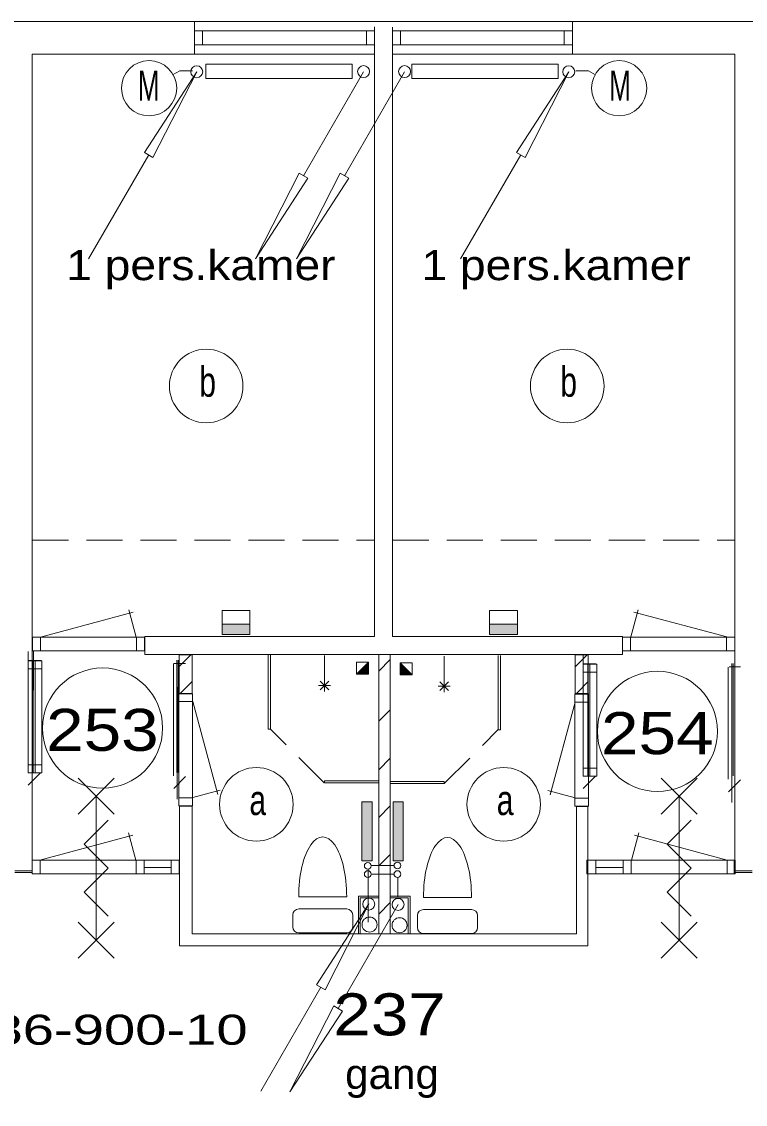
# Model space of a CAD drawing. Extents: x 295824 to 414724, y 24924 to 109024.
# Drawn here: x 314001 to 320029, y 95404 to 104418 of the extents above; entities that cross this region are included whole.
import ezdxf
from ezdxf.enums import TextEntityAlignment as Align

# ---------------------------------------------------------------- set-up
doc = ezdxf.new("R2010")
doc.units = 0
doc.header["$LTSCALE"] = 100
doc.linetypes.add('LONG_DASHED', pattern=[7.5, 6, -1.5])
doc.linetypes.add('MEDIUM_DASHED', pattern=[4.5, 3, -1.5])
doc.layers.add('16', color=7, linetype='Continuous', lineweight=13)
doc.layers.add('61', color=7, linetype='Continuous', lineweight=13)

msp = doc.modelspace()

# ---------------------------------------------------------------- hatches: boundary and pattern name
at = {"layer": '16'}
for points in [[(315902.2, 99315.2), (315670.7, 99315.2), (315670.7, 99401.7), (315902.2, 99401.7)], [(318129.9, 99315.2), (317898.4, 99315.2), (317898.4, 99401.7), (318129.9, 99401.7)], [(316835.4, 97923), (316920.8, 97923), (316920.8, 97430.8), (316835.4, 97430.8)], [(317094.6, 97923), (317180, 97923), (317180, 97430.8), (317094.6, 97430.8)]]:
    msp.add_hatch(color=256, dxfattribs=at).paths.add_polyline_path(points)
at = {"layer": '61'}
for points in [[(316790.6, 98985.1), (316890.6, 99085.1), (316890.6, 98985.1)], [(317253, 98979.7), (317153, 99079.7), (317153, 98979.7)]]:
    msp.add_hatch(color=256, dxfattribs=at).paths.add_polyline_path(points)

# ---------------------------------------------------------------- linework, layer by layer
at = {"layer": '16'}
for p, q in [((316849.4, 104000.9), (316349.4, 103134.9)), ((317191, 104000.9), (316691, 103134.9)), ((314559.2, 102441.9), (315059.2, 103307.9)), ((317657.6, 102441.9), (318157.6, 103307.9)), ((315670.7, 99401.7), (315670.7, 99515.6)), ((317898.4, 99401.7), (317898.4, 99515.6)), ((316887.6, 96920.1), (316887.6, 97360.2)), ((317103, 97392), (316911.2, 97392)), ((317136.2, 97067.7), (316636.2, 96201.7)), ((315992.3, 95512.9), (316492.3, 96378.9))]:
    msp.add_line(p, q, dxfattribs=at)
at = {"layer": '16', "linetype": 'LONG_DASHED'}
for p, q in [((316911.4, 97321.2), (317102.9, 97321.2)), ((317133.8, 97131.9), (317133.8, 97295.5))]:
    msp.add_line(p, q, dxfattribs=at)
at = {"layer": '16'}
for points in [[(315536, 103945.4), (316755.3, 103945.4), (316755.3, 104063.3), (315536, 104063.3)], [(317251.6, 103945.4), (318470.9, 103945.4), (318470.9, 104063.3), (317251.6, 104063.3)], [(315459.2, 104000.9), (315095.2, 103286.9), (315023.2, 103328.9)], [(318557.6, 104000.9), (318193.6, 103286.9), (318121.6, 103328.9)], [(315949.4, 102441.9), (316313.4, 103155.9), (316385.4, 103113.9)], [(316291, 102441.9), (316655, 103155.9), (316727, 103113.9)], [(315902.2, 99315.2), (315670.7, 99315.2), (315670.7, 99401.7), (315902.2, 99401.7)], [(318129.9, 99315.2), (317898.4, 99315.2), (317898.4, 99401.7), (318129.9, 99401.7)], [(316835.4, 97923), (316920.8, 97923), (316920.8, 97430.8), (316835.4, 97430.8)], [(317094.6, 97923), (317180, 97923), (317180, 97430.8), (317094.6, 97430.8)], [(316892.3, 97071.9), (316528.3, 96357.9), (316456.3, 96399.9)], [(316236.2, 95508.7), (316600.2, 96222.7), (316672.2, 96180.7)]]:
    msp.add_lwpolyline(points, close=True, dxfattribs=at)
for points in [[(315423.8, 104008.7), (315317.8, 104008.7), (315258.3, 103974.4)], [(318616.5, 104008.7), (318722.6, 104008.7), (318782.1, 103974.4)], [(315902.2, 99401.7), (315902.2, 99515.6), (315670.7, 99515.6)], [(318129.9, 99401.7), (318129.9, 99515.6), (317898.4, 99515.6)]]:
    msp.add_lwpolyline(points, dxfattribs=at)
for centre, radius in [((315062.7, 103863.4), 229.9), ((315459.1, 104000.6), 50), ((316849.4, 104001.3), 50), ((317191, 104001.3), 50), ((318557.6, 104000.6), 50), ((318977.7, 103863.4), 229.9), ((316883.5, 97389), 27.9), ((316883.5, 97321.2), 27.9), ((317130.9, 97392), 27.9), ((317130.9, 97321.2), 27.9), ((316892.3, 97071.6), 50), ((317136.2, 97068), 50)]:
    msp.add_circle(centre, radius, dxfattribs=at)
at = {"layer": '61'}
for p, q in [((315441, 104147.6), (315441, 104417.6)), ((318589.5, 104147.6), (318589.5, 104417.6)), ((315508.1, 104225.9), (315508.1, 104339.8)), ((316873.1, 104225.3), (316873.1, 104339.3)), ((316940.1, 104375), (316940.1, 99297.6)), ((317090.1, 104371.2), (317090.1, 99297.6)), ((317156.6, 104226.2), (317156.6, 104340.2)), ((318520.9, 104225.9), (318520.9, 104339.6)), ((314090.1, 104147.6), (316940.1, 104147.6)), ((314090.1, 97436.7), (314090.1, 104147.6)), ((319940.1, 104147.6), (317090.1, 104147.6)), ((319940.1, 97436.7), (319940.1, 104147.6)), ((314955.9, 99294.3), (314895.1, 99521.1)), ((319075.3, 99295.4), (319136, 99522.2)), ((314157.5, 99293.7), (314930.2, 99500.7)), ((319873.7, 99294.8), (319101, 99501.8)), ((314158.2, 99179), (314158.2, 99293)), ((314958.2, 99179), (314958.2, 99293)), ((315025.2, 99179), (315025.2, 99293)), ((319005.9, 99180.1), (319005.9, 99294.1)), ((319072.9, 99180.1), (319072.9, 99294.1)), ((319872.9, 99180.1), (319872.9, 99294.1)), ((314056.5, 98850.8), (314056.5, 99174.9)), ((314099.2, 98850.8), (314099.2, 99174.9)), ((314163.1, 99100), (314057.9, 99100)), ((314096.6, 98163.9), (314096.6, 99096.4)), ((314112.5, 98163.9), (314112.5, 99096.4)), ((314169.1, 98163.9), (314169.1, 99096.4)), ((315264.9, 98138.7), (315264.9, 99072.7)), ((315367.2, 99073.5), (315272.4, 99073.5)), ((315293.7, 98166.6), (315293.7, 99100.6)), ((315304.8, 98166.6), (315304.8, 99100.6)), ((315310.4, 99046.8), (315410.1, 99146.5)), ((315311.9, 98823), (315311.9, 99147)), ((315311.9, 99147), (315421.9, 99147)), ((315421.9, 98823), (315421.9, 99147)), ((316073.1, 99147.4), (316073.1, 98526.9)), ((316523, 98940.9), (316523, 99140.9)), ((316975, 99147.6), (316975, 96822.6)), ((316975.5, 99011.5), (317071.3, 99107.3)), ((317071.3, 99147.6), (317071.3, 96822.6)), ((317520.7, 98935.5), (317520.7, 99135.5)), ((317970.5, 99142), (317970.5, 98521.5)), ((318610.9, 98823), (318610.9, 99147)), ((318610.9, 99147), (318720.8, 99147)), ((318612.6, 99046.8), (318712.3, 99146.5)), ((318678.1, 98823), (318678.1, 99147)), ((318784.8, 99072.1), (318679.5, 99072.1)), ((318718.2, 98136.1), (318718.2, 99068.5)), ((318720.8, 98823), (318720.8, 99147)), ((318734.1, 98136.1), (318734.1, 99068.5)), ((318790.7, 98136.1), (318790.7, 99068.5)), ((319915.4, 98138.8), (319915.4, 99072.8)), ((319926.4, 98138.8), (319926.4, 99072.8)), ((314169.1, 99029.4), (314055.1, 99029.4)), ((318790.7, 99001.5), (318676.7, 99001.5)), ((319886.5, 98110.9), (319886.5, 99044.9)), ((319988.8, 99045.7), (319894, 99045.7)), ((315322.7, 98824.2), (315422.4, 98923.9)), ((316573, 98890.9), (316473, 98890.9)), ((316558.4, 98926.2), (316487.6, 98855.5)), ((316558.4, 98855.5), (316487.6, 98926.2)), ((316523, 98940.9), (316523, 98840.9)), ((317470.7, 98885.5), (317570.7, 98885.5)), ((317485.3, 98920.9), (317556.1, 98850.2)), ((317485.3, 98850.2), (317556.1, 98920.9)), ((317520.7, 98935.5), (317520.7, 98835.5)), ((318621.2, 98824.2), (318720.9, 98923.9)), ((315295.2, 98877.8), (315295.2, 97945.4)), ((315310.1, 98822.1), (315310.1, 97889.7)), ((315311.9, 98823), (315421.9, 98823)), ((318610.2, 98819.4), (318724.2, 98819.4)), ((318610.9, 98823), (318720.8, 98823)), ((318723.6, 98819.4), (318723.6, 97885.4)), ((319916.9, 98850), (319916.9, 97917.6)), ((315310.1, 98756.7), (315424.1, 98756.7)), ((315427.3, 98757.4), (315634.3, 97984.7)), ((318611.5, 98753.2), (318404.5, 97980.5)), ((318723.6, 98752.4), (318609.6, 98752.4)), ((316975.5, 98593.4), (317071.3, 98689.2)), ((316975.5, 98188.8), (317071.3, 98284.6)), ((314169.1, 98229.4), (314055.1, 98229.4)), ((314156.5, 98161.9), (314056.8, 98062.2)), ((314167.3, 98163.1), (314057.3, 98163.1)), ((318790.7, 98201.5), (318676.7, 98201.5)), ((314772.1, 98119.9), (314472.1, 97819.9)), ((314472.1, 98119.9), (314772.1, 97819.9)), ((315367.3, 98134), (315267.6, 98034.3)), ((316973.2, 98097.4), (316524, 98097.4)), ((316524, 98079.4), (316524, 98097.4)), ((316973.5, 98079.4), (316524, 98079.4)), ((317070.2, 98074), (317519.7, 98074)), ((317070.5, 98092), (317519.7, 98092)), ((317519.7, 98074), (317519.7, 98092)), ((318778.1, 98134), (318678.4, 98034.3)), ((318788.9, 98135.2), (318679, 98135.2)), ((319628, 98119.9), (319328, 97819.9)), ((319328, 98119.9), (319628, 97819.9)), ((319988.9, 98106.1), (319889.2, 98006.4)), ((315427.9, 97959), (315654.8, 98019.8)), ((318610.9, 97954.8), (318384, 98015.6)), ((314622.1, 96769.9), (314622.1, 97969.9)), ((315310.1, 97956.7), (315424.1, 97956.7)), ((318723.6, 97952.4), (318609.6, 97952.4)), ((319478, 96769.9), (319478, 97969.9)), ((315316.1, 97886.1), (315316.1, 97320.2)), ((315316.1, 97886.1), (315421.3, 97886.1)), ((316975.5, 97792.8), (317071.3, 97888.6)), ((318621.3, 97884.6), (318621.3, 96822.6)), ((318621.3, 97884.6), (318716.1, 97884.6)), ((318716.1, 97884.6), (318716.1, 97422.6)), ((314154.1, 97437.3), (314926.9, 97644.4)), ((314952.5, 97437.9), (314891.8, 97664.8)), ((319079.9, 97437.9), (319140.6, 97664.8)), ((319878.3, 97437.3), (319105.5, 97644.4)), ((316975.5, 97389.4), (317071.3, 97485.2)), ((313944.8, 97348.9), (314086, 97348.9)), ((314154.9, 97322.7), (314154.9, 97436.7)), ((314954.9, 97322.7), (314954.9, 97436.7)), ((315021.9, 97322.7), (315021.9, 97436.7)), ((315247.9, 97376.8), (315021.9, 97376.8)), ((315247.9, 97322.7), (315247.9, 97436.7)), ((318784.5, 97322.7), (318784.5, 97436.7)), ((318784.5, 97376.8), (319010.5, 97376.8)), ((319010.5, 97322.7), (319010.5, 97436.7)), ((319077.5, 97322.7), (319077.5, 97436.7)), ((319877.5, 97322.7), (319877.5, 97436.7)), ((319943.6, 97348.9), (320084.8, 97348.9)), ((313944.8, 97333.9), (314086, 97333.9)), ((319943.6, 97333.9), (320084.8, 97333.9)), ((316708.7, 97130.5), (316308.7, 97130.5)), ((316821.2, 97123.1), (316971.2, 97123.1)), ((316821.2, 96823.1), (316821.2, 97123.1)), ((316975.5, 96988.5), (317071.3, 97084.3)), ((317071.3, 97122.6), (317221.3, 97122.6)), ((317221.3, 97122.6), (317221.3, 96822.6)), ((317748.1, 97125.6), (317348.1, 97125.6)), ((316308.7, 97030.5), (316708.7, 97030.5)), ((317348.1, 97025.6), (317748.1, 97025.6)), ((314772.1, 96919.9), (314472.1, 96619.9)), ((314472.1, 96919.9), (314772.1, 96619.9)), ((316258.7, 96880.5), (316258.7, 96980.5)), ((316758.7, 96980.5), (316758.7, 96880.5)), ((317298.1, 96875.6), (317298.1, 96975.6)), ((317798.1, 96975.6), (317798.1, 96875.6)), ((319628, 96919.9), (319328, 96619.9)), ((319328, 96919.9), (319628, 96619.9)), ((316708.7, 96830.5), (316308.7, 96830.5)), ((317748.1, 96825.6), (317348.1, 96825.6))]:
    msp.add_line(p, q, dxfattribs=at)
at = {"layer": '61', "linetype": 'MEDIUM_DASHED'}
for p, q in [((314090.7, 100101), (316939.8, 100101)), ((317093.1, 100101), (319940.1, 100101)), ((316522, 98079.8), (316075.1, 98526.7)), ((317521.7, 98074.4), (317968.6, 98521.3))]:
    msp.add_line(p, q, dxfattribs=at)
at = {"layer": '61'}
for points in [[(301796.6, 92184.5), (301820.1, 104417.6), (332210.1, 104417.6)], [(314091.2, 99179), (314091.2, 99293), (315025.2, 99293)], [(315025.2, 99179), (314091.2, 99179), (314091.2, 99293)], [(316941.1, 99297.6), (315026, 99297.6), (315026, 99147.6), (319005.4, 99147.6)], [(317091.1, 99297.6), (319005.4, 99297.6), (319005.4, 99147.6)], [(319939.9, 99180.1), (319939.9, 99294.1), (319005.9, 99294.1)], [(319005.9, 99180.1), (319939.9, 99180.1), (319939.9, 99294.1)], [(316055.1, 99147.4), (316055.1, 98526.9), (316073.1, 98526.9)], [(316890.6, 99085.1), (316890.6, 98985.1), (316790.6, 98985.1)], [(317153, 99079.7), (317153, 98979.7), (317253, 98979.7)], [(317988.5, 99142), (317988.5, 98521.5), (317970.5, 98521.5)], [(315421.3, 97886.1), (315421.3, 96822.6), (318621.3, 96822.6)], [(314722.1, 96969.9), (314522.1, 97169.9), (314722.1, 97369.9), (314522.1, 97569.9), (314722.1, 97769.9)], [(319578, 96969.9), (319378, 97169.9), (319578, 97369.9), (319378, 97569.9), (319578, 97769.9)], [(315316.1, 97322.6), (315316.1, 96722.6), (318716.1, 96722.6), (318716.1, 97322.6)], [(316806.2, 96823.1), (316806.2, 97138.1), (316971.2, 97138.1)], [(317071.3, 97137.6), (317236.3, 97137.6), (317236.3, 96822.6)]]:
    msp.add_lwpolyline(points, dxfattribs=at)
for points in [[(315441.2, 104225.8), (315441.2, 104339.8), (316939.9, 104339.8), (316939.9, 104225.8)], [(317090.2, 104225.9), (317090.2, 104339.9), (318589.6, 104339.9), (318589.6, 104225.9)], [(314169.1, 99097.3), (314055.1, 99097.3), (314055.1, 98163.3), (314169.1, 98163.3)], [(316890.6, 99085.1), (316790.6, 99085.1), (316790.6, 98985.1)], [(316790.6, 98985.1), (316890.6, 99085.1), (316890.6, 98985.1)], [(317153, 99079.7), (317253, 99079.7), (317253, 98979.7)], [(317253, 98979.7), (317153, 99079.7), (317153, 98979.7)], [(318790.7, 99069.4), (318676.7, 99069.4), (318676.7, 98135.4), (318790.7, 98135.4)], [(315310.1, 97888.7), (315424.1, 97888.7), (315424.1, 98822.7), (315310.1, 98822.7)], [(318723.6, 98819.4), (318723.6, 97885.4), (318609.6, 97885.4), (318609.6, 98819.4)], [(314087.9, 97322.7), (314087.9, 97436.7), (315314.2, 97436.7), (315314.2, 97322.7)], [(314087.9, 97322.7), (314087.9, 97436.7), (315314.2, 97436.7), (315314.2, 97322.7)], [(318709.2, 97322.7), (318709.2, 97436.7), (319936.2, 97436.7), (319936.2, 97322.7)], [(318717.5, 97322.7), (318717.5, 97436.7), (319944.5, 97436.7), (319944.5, 97322.7)]]:
    msp.add_lwpolyline(points, close=True, dxfattribs=at)
for centre, radius in [((315538.5, 101384.2), 306.3), ((318545.3, 101384.2), 306.3), ((314675.2, 98536.8), 500), ((319296.8, 98509), 500), ((315956.1, 97901.5), 306.3), ((318016.4, 97901.5), 306.3), ((316898.8, 96900.6), 62.5), ((317148.8, 96895), 62.5)]:
    msp.add_circle(centre, radius, dxfattribs=at)
for centre, start, end in [((316308.7, 96980.5), 90, 180), ((316708.7, 96980.5), 0, 90), ((317348.1, 96975.6), 90, 180), ((317748.1, 96975.6), 0, 90), ((316308.7, 96880.5), 180, 270), ((316708.7, 96880.5), 270, 0), ((317348.1, 96875.6), 180, 270), ((317748.1, 96875.6), 270, 0)]:
    msp.add_arc(centre, 50, start, end, dxfattribs=at)
for centre in [(316508.7, 97130.5), (317548.1, 97125.6)]:
    msp.add_ellipse(centre, major_axis=(0, 500), ratio=0.4, start_param=4.712389, end_param=7.853982, dxfattribs=at)

# ---------------------------------------------------------------- texts
at = {"layer": '16'}
for s, width, p in [('M', 0.65, (314968.7, 103760.3)), ('M', 0.65, (318894.5, 103760.3)), ('14x 486-900-10', 1.4, (312605.1, 95900.2))]:
    msp.add_text(s, height=250, dxfattribs=dict(at, width=width)).set_placement(p)
at = {"layer": '61'}
for s, height, width, p in [('1 pers.kamer', 250, 1.15, (314372.5, 102265.6)), ('1 pers.kamer', 250, 1.15, (317330.9, 102265.6)), ('b', 250, 0.75, (315480.5, 101295)), ('b', 250, 0.75, (318487.3, 101295)), ('a', 250, 0.75, (315898.1, 97812.3)), ('a', 250, 0.75, (317958.4, 97812.3)), ('237', 350, 1.2, (316597.2, 95978.1)), ('gang', 250, 1.05, (316695.7, 95532.1))]:
    msp.add_text(s, height=height, dxfattribs=dict(at, width=width)).set_placement(p)
at = {"layer": '61', "width": 1.2}
for s, p in [('253', (314673.7, 98346.9)), ('254', (319295.3, 98319.1))]:
    msp.add_text(s, height=350, dxfattribs=at).set_placement(p, align=Align.CENTER)

doc.saveas('drawing.dxf')
